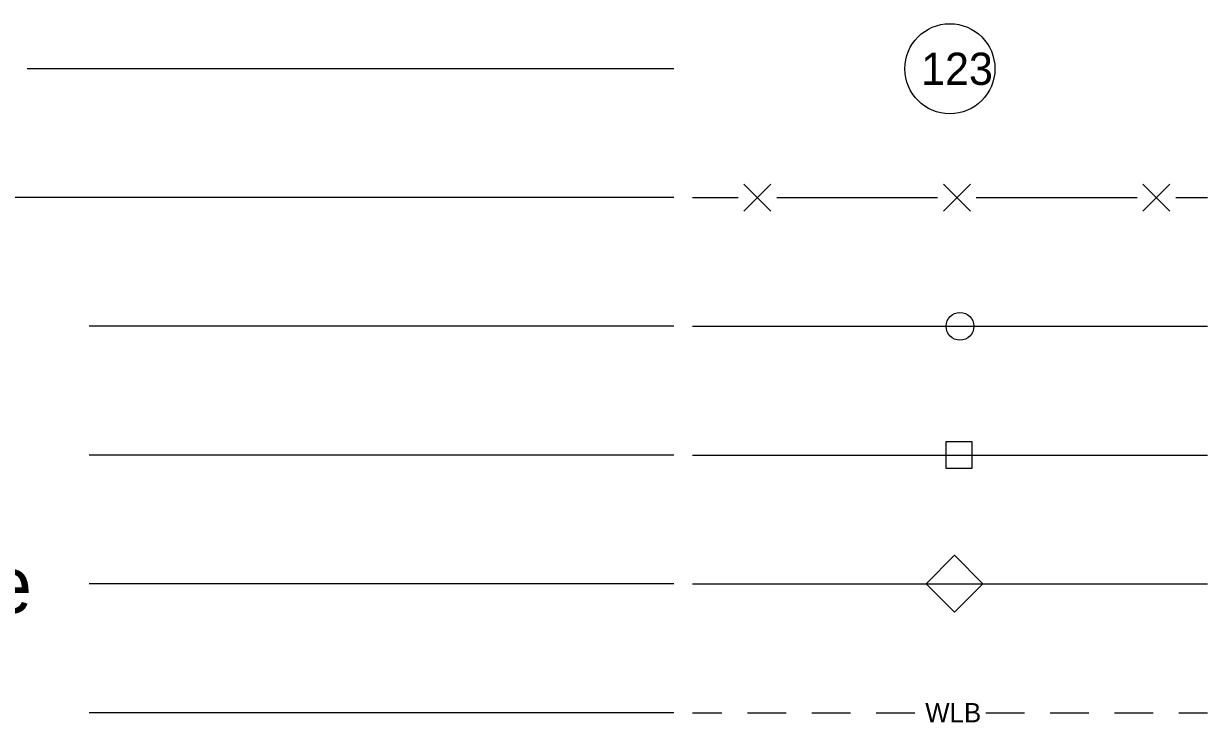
# Model space of a CAD drawing. Extents: x -0.53 to 3.34, y -0.27 to 4.33.
# Drawn here: x 0.5753 to 0.8846, y 3.6765 to 3.8589 of the extents above; entities that cross this region are included whole.
import ezdxf

# ---------------------------------------------------------------- set-up
doc = ezdxf.new("R2010")
doc.units = 0
doc.layers.add('Sheet_Symbology', color=7, linetype='Continuous')

msp = doc.modelspace()

# ---------------------------------------------------------------- linework, layer by layer
at = {"layer": 'Sheet_Symbology'}
for p, q in [((0.7452, 3.84715), (0.57622, 3.84715)), ((0.76348, 3.80999), (0.77055, 3.81705)), ((0.77055, 3.80999), (0.76348, 3.81705)), ((0.81561, 3.80999), (0.82268, 3.81705)), ((0.82268, 3.80999), (0.81561, 3.81705)), ((0.86774, 3.80999), (0.8748, 3.81705)), ((0.8748, 3.80999), (0.86774, 3.81705)), ((0.7452, 3.81352), (0.50118, 3.81352)), ((0.75003, 3.81352), (0.76197, 3.81352)), ((0.77206, 3.81352), (0.79308, 3.81352)), ((0.79308, 3.81352), (0.8141, 3.81352)), ((0.82419, 3.81352), (0.84521, 3.81352)), ((0.84521, 3.81352), (0.86623, 3.81352)), ((0.87632, 3.81352), (0.88456, 3.81352)), ((0.7452, 3.77989), (0.59245, 3.77989)), ((0.75003, 3.77989), (0.88456, 3.77989)), ((0.75003, 3.77989), (0.88456, 3.77989)), ((0.7452, 3.74626), (0.59245, 3.74626)), ((0.75003, 3.74626), (0.88456, 3.74626)), ((0.75003, 3.74626), (0.88456, 3.74626)), ((0.7452, 3.71262), (0.59245, 3.71262)), ((0.75003, 3.71262), (0.88456, 3.71262)), ((0.75003, 3.71262), (0.88456, 3.71262)), ((0.7452, 3.67899), (0.59245, 3.67899)), ((0.75003, 3.67899), (0.75773, 3.67899)), ((0.76445, 3.67899), (0.77454, 3.67899)), ((0.78127, 3.67899), (0.79136, 3.67899)), ((0.79808, 3.67899), (0.80817, 3.67899)), ((0.82667, 3.67899), (0.83676, 3.67899)), ((0.84349, 3.67899), (0.85357, 3.67899)), ((0.8603, 3.67899), (0.87039, 3.67899)), ((0.87712, 3.67899), (0.88456, 3.67899))]:
    msp.add_line(p, q, dxfattribs=at)
for points in [[(0.81624, 3.74281), (0.82314, 3.74281), (0.82314, 3.7497), (0.81624, 3.7497)], [(0.81847, 3.70522), (0.82587, 3.71262), (0.81847, 3.72011), (0.81107, 3.71262)]]:
    msp.add_lwpolyline(points, close=True, dxfattribs=at)
for centre, radius in [((0.81729, 3.84715), 0.01177), ((0.81994, 3.77989), 0.00362)]:
    msp.add_circle(centre, radius, dxfattribs=at)

# ---------------------------------------------------------------- texts
for s, height, p in [('123', 0.008408, (0.80977, 3.84294)), ('Proposed Barbed Wire Fence', 0.0147137, (0.31829, 3.70499)), ('WLB', 0.005045, (0.81086, 3.67647))]:
    msp.add_text(s, height=height, dxfattribs=at).set_placement(p)

doc.saveas('drawing.dxf')
